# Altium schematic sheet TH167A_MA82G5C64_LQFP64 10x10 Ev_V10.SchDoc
size 289 x 209 mm; PageSetup: Record=PageOptions|CenterHorizontal=True|CenterVertical=True|PrintScale=0.99|XCorrection=1.00|YCorrection=1.00|PrintKind=0|BorderSize=5000000|LeftOffset=0|BottomOffset=0|Orientation=2|PaperLength=1000|PaperWidth=1000|Scale=100|PaperSource=7|PrintQuality=-4|MediaType=1|DitherType=10|PaperKind=A4|PrintScaleMode=1
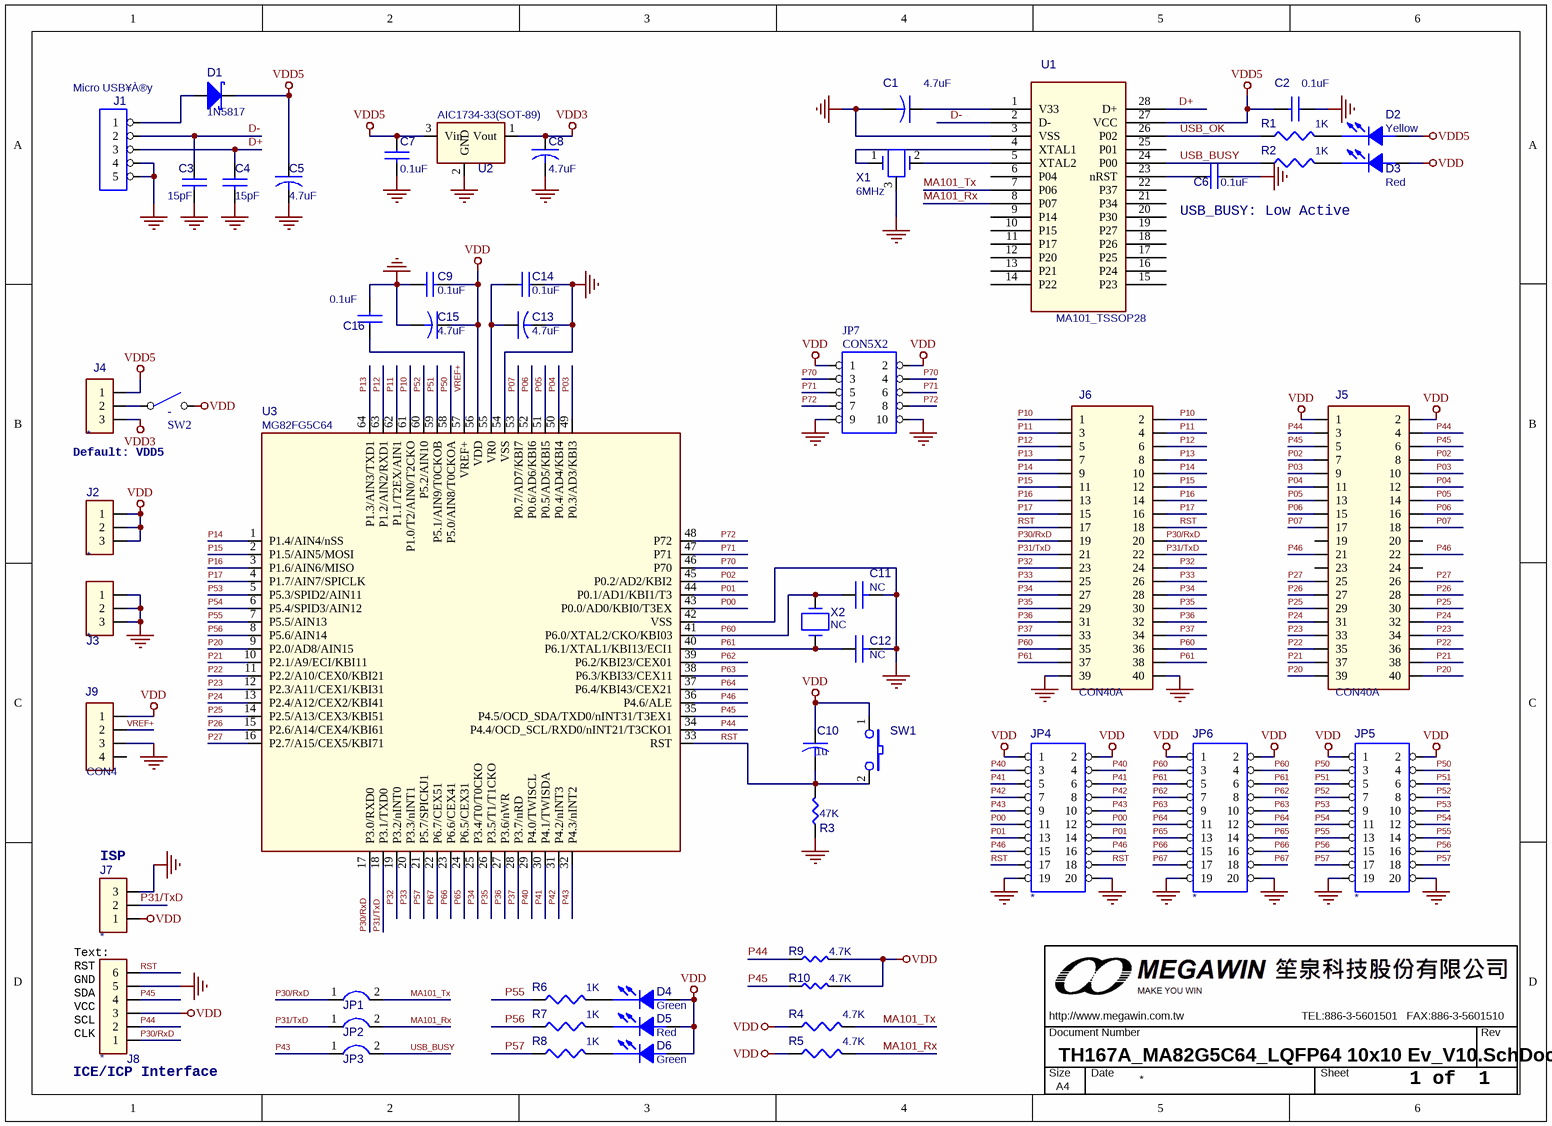
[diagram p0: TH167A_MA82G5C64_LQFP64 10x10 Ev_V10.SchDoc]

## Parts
C1  4.7uF  [0805C]
C2  0.1uF  [0805C]
C3  15pF  [0805C]
C4  15pF  [0805C]
C5  4.7uF  [1206C]
C6  0.1uF  [0805C]
C7  0.1uF  [0805C]
C8  4.7uF  [0805C]
C9  0.1uF  [0805C]
C10  1u  [0805C]
C11  NC  [0805C]
C12  NC  [0805C]
C13  4.7uF  [0805C]
C14  0.1uF  [0805C]
C15  4.7uF  [0805C]
C16  0.1uF  [0805C]
D1  1N5817  [D5817_SMD_1]
D2  Yellow  [0805D]
D3  Red  [0805D]
D4  Green  [0805D]
D5  Red  [0805D]
D6  Green  [0805D]
J1  Micro USB¥À®y  [JACK_USB_SMD290X220P065]
J2  *  [PS3P254]
J3  *  [PS3P254]
J4  *  [JUMP3_SMD]
J5  CON40A  [PS20X2P254]
J6  CON40A  [PS20X2P254]
J7  *  [PS3P254f_90]
J8  *  [PS6P254F_90]
J9  CON4  [PS4p254]
JP1  JUMPER2  [PS2P254]  (value not drawn)
JP2  JUMPER2  [PS2P254]  (value not drawn)
JP3  JUMPER2  [PS2P254]  (value not drawn)
JP4  *  [PS10X2P254]
JP5  *  [PS10X2P254]
JP6  *  [PS10X2P254]
JP7  CON5X2  [PS5X2P254]
MW1  OrgAddr3: TEL:886-3-5601501   FAX:886-3-5601510  Page Size: A4  [MEGAWIN10_1]  (hidden comment: MW_A4_1)  (graphical)
R1  1K  [0805R]
R2  1K  [0805R]
R3  47K  [0805R]
R4  4.7K  [0805R]
R5  4.7K  [0805R]
R6  1K  [0805R]
R7  1K  [0805R]
R8  1K  [0805R]
R9  4.7K  [0805R]
R10  4.7K  [0805R]
SW1  SW TACT-SPST  [SW_T_2P]  (value not drawn)
SW2  -  [DIP2_SW]
U1  MA101_TSSOP28  [SSOP28_220P065]
U2  AIC1734-33(SOT-89)  [SOT89]
U3  MG82FG5C64  [QFP64_10X10P050]
X1  6MHz  [X3P]
X2  NC  [X49U]

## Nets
GND_POWER: C1.2 C2.1 C3.2 C4.2 C5.2 C6.1 C7.2 C8.2 C9.1 C11.2 C12.2 C13.2 C14.1 C15.2 C16.2 J1.4 J1.5 J3.1 J3.2 J3.3 J6.39 J6.40 J7.3 J8.5 J9.3 JP4.19 JP4.20 JP5.19 JP5.20 JP6.19 JP6.20 JP7.9 JP7.10 R3.1 U1.3(VSS) U2.2(GND) U3.42(VSS) U3.54(VSS) X1.3
VDD: C9.2 C10.1(POS) C15.1 D3.1(ANODE) D4.1(ANODE) D5.1(ANODE) D6.1(ANODE) J2.1 J2.2 J2.3 J5.1 J5.2 J7.1 J8.3 J9.1 JP4.1 JP4.2 JP5.1 JP5.2 JP6.1 JP6.2 JP7.1 JP7.2 R4.1 R5.1 R9.2 R10.2 SW1.1 SW2.2(NO) U3.56(VDD)
VDD3: C8.1 J4.3 U2.1(Vout)
VDD5: C2.2 C5.1 C7.1 D1.2(K) D2.1(ANODE) J4.1 U1.27(VCC) U2.3(Vin)
D+: C4.1 J1.3 U1.28(D+)
D-: C3.1 J1.2 U1.2(D-)
MA101_Rx: JP2.2 R5.2 U1.8(P07)
MA101_Tx: JP1.2 R4.2 U1.7(P06)
P00: JP4.11 JP4.12 U3.43(P0.0/AD0/KBI0/T3EX)
P01: JP4.13 JP4.14 U3.44(P0.1/AD1/KBI1/T3)
P02: J5.7 J5.8 U3.45(P0.2/AD2/KBI2)
P03: J5.9 J5.10 U3.49(P0.3/AD3/KBI3)
P04: J5.11 J5.12 U3.50(P0.4/AD4/KBI4)
P05: J5.13 J5.14 U3.51(P0.5/AD5/KBI5)
P06: J5.15 J5.16 U3.52(P0.6/AD6/KBI6)
P07: J5.17 J5.18 U3.53(P0.7/AD7/KBI7)
P10: J6.1 J6.2 U3.61(P1.0/T2/AIN0/T2CKO)
P11: J6.3 J6.4 U3.62(P1.1/T2EX/AIN1)
P12: J6.5 J6.6 U3.63(P1.2/AIN2/RXD1)
P13: J6.7 J6.8 U3.64(P1.3/AIN3/TXD1)
P14: J6.9 J6.10 U3.1(P1.4/AIN4/nSS)
P15: J6.11 J6.12 U3.2(P1.5/AIN5/MOSI)
P16: J6.13 J6.14 U3.3(P1.6/AIN6/MISO)
P17: J6.15 J6.16 U3.4(P1.7/AIN7/SPICLK)
P20: J5.39 J5.40 U3.9(P2.0/AD8/AIN15)
P21: J5.37 J5.38 U3.10(P2.1/A9/ECI/KBI11)
P22: J5.35 J5.36 U3.11(P2.2/A10/CEX0/KBI21)
P23: J5.33 J5.34 U3.12(P2.3/A11/CEX1/KBI31)
P24: J5.31 J5.32 U3.13(P2.4/A12/CEX2/KBI41)
P25: J5.29 J5.30 U3.14(P2.5/A13/CEX3/KBI51)
P26: J5.27 J5.28 U3.15(P2.6/A14/CEX4/KBI61)
P27: J5.25 J5.26 U3.16(P2.7/A15/CEX5/KBI71)
P30/RxD: J6.19 J6.20 J8.1 JP1.1 U3.17(P3.0/RXD0)
P31/TxD: J6.21 J6.22 J7.2 JP2.1 U3.18(P3.1/TXD0)
P32: J6.23 J6.24 U3.19(P3.2/nINT0)
P33: J6.25 J6.26 U3.20(P3.3/nINT1)
P34: J6.27 J6.28 U3.25(P3.4/T0/T0CKO)
P35: J6.29 J6.30 U3.26(P3.5/T1/T1CKO)
P36: J6.31 J6.32 U3.27(P3.6/nWR)
P37: J6.33 J6.34 U3.28(P3.7/nRD)
P40: JP4.3 JP4.4 U3.29(P4.0/TWISCL)
P41: JP4.5 JP4.6 U3.30(P4.1/TWISDA)
P42: JP4.7 JP4.8 U3.31(P4.2/nINT3)
P43: JP3.1 JP4.9 JP4.10 U3.32(P4.3/nINT2)
P44: J5.3 J5.4 J8.2 R9.1 U3.34(P4.4/OCD_SCL/RXD0/nINT21/T3CKO1)
P45: J5.5 J5.6 J8.4 R10.1 U3.35(P4.5/OCD_SDA/TXD0/nINT31/T3EX1)
P46: J5.21 J5.22 JP4.15 JP4.16 U3.36(P4.6/ALE)
P50: JP5.3 JP5.4 U3.58(P5.0/AIN8/T0CKOA)
P51: JP5.5 JP5.6 U3.59(P5.1/AIN9/T0CKOB)
P52: JP5.7 JP5.8 U3.60(P5.2/AIN10)
P53: JP5.9 JP5.10 U3.5(P5.3/SPID2/AIN11)
P54: JP5.11 JP5.12 U3.6(P5.4/SPID3/AIN12)
P55: JP5.13 JP5.14 R6.1 U3.7(P5.5/AIN13)
P56: JP5.15 JP5.16 R7.1 U3.8(P5.6/AIN14)
P57: JP5.17 JP5.18 R8.1 U3.21(P5.7/SPICKJ1)
P60: C11.1 J6.35 J6.36 JP6.3 JP6.4 U3.41(P6.0/XTAL2/CKO/KBI03) X2.2
P61: C12.1 J6.37 J6.38 JP6.5 JP6.6 U3.40(P6.1/XTAL1/KBI13/ECI1) X2.1
P62: JP6.7 JP6.8 U3.39(P6.2/KBI23/CEX01)
P63: JP6.9 JP6.10 U3.38(P6.3/KBI33/CEX11)
P64: JP6.11 JP6.12 U3.37(P6.4/KBI43/CEX21)
P65: JP6.13 JP6.14 U3.24(P6.5/CEX31)
P66: JP6.15 JP6.16 U3.23(P6.6/CEX41)
P67: JP6.17 JP6.18 U3.22(P6.7/CEX51)
P70: JP7.3 JP7.4 U3.46(P70)
P71: JP7.5 JP7.6 U3.47(P71)
P72: JP7.7 JP7.8 U3.48(P72)
RST: C10.2(NEG) J6.17 J6.18 J8.6 JP4.17 JP4.18 R3.2 SW1.2 U3.33(RST)
USB_BUSY: JP3.2 R2.1 U1.24(P00)
USB_OK: R1.1 U1.26(P02)
VREF+: C16.1 J9.2 U3.57(VREF+)
NetC1_1: C1.1 U1.1(V33)
NetC6_2: C6.2 U1.23(nRST)
NetC13_1: C13.1 C14.2 U3.55(VR0)
NetD1_1: D1.1(A) J1.1
NetD2_2: D2.2(CATHODE) R1.2
NetD3_2: D3.2(CATHODE) R2.2
NetD4_2: D4.2(CATHODE) R6.2
NetD5_2: D5.2(CATHODE) R7.2
NetD6_2: D6.2(CATHODE) R8.2
NetJ4_2: J4.2 SW2.1(COMMON)
NetU1_4: U1.4(XTAL1) X1.1
NetU1_5: U1.5(XTAL2) X1.2

Not connected (* = marked no-connect by the designer): J5 19 20 23 24; J9 4; U1 6(P04) 9(P14) 10(P15) 11(P17) 12(P20) 13(P21) 14(P22) 15(P23) 16(P24) 17(P25) 18(P26) 19(P27) 20(P30) 21(P34) 22(P37) 25(P01)

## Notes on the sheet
- USB_BUSY: Low Active
- Default: VDD5
- (near J7) ISP
- (near J8) ICE/ICP Interface
- Text:
  RST
  GND
  SDA
  VCC
  SCL
  CLK
- 1 of  1

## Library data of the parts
C1 C5 C8 C13 C15 = CAP
C2-C4 C6 C7 C9 C14 C16 = CAP NP
C10 = C
C11 C12 = C NP
D1 = DIODE_ZD: Schottky Diode
D2-D6 = LED
J1 = CON5: Connector
J2-J4 J7 = CON3
J8 = CON6
JP4-JP6 = CON10X2
R1 R2 R4-R8 = R_Dup1
R3 R9 R10 = R
SW2 = SW-2
U2 = AIC1734-33(SOT-89)_0
U3 = MG82FG5C64_LQFP64
X1 = CRYSTAL_RC
X2 = CRYSTAL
